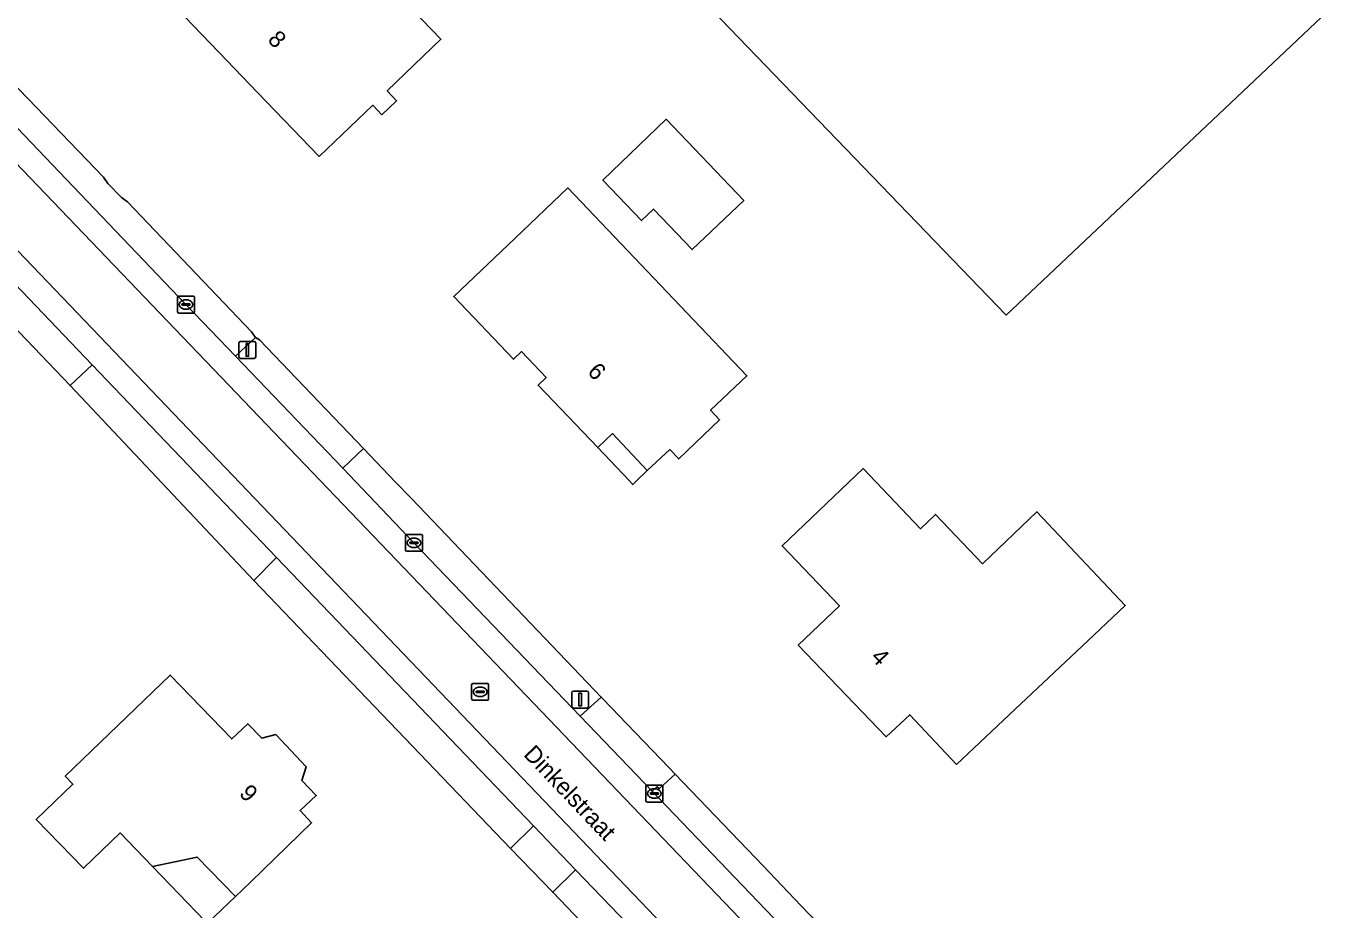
# Model space of a CAD drawing. Extents: x 156702 to 158052, y 387630 to 388992.
# Drawn here: x 157527.1 to 157604.6, y 388153.2 to 388205.4 of the extents above; entities that cross this region are included whole.
import ezdxf

# ---------------------------------------------------------------- set-up
doc = ezdxf.new("R2010")
doc.units = 0
for name, color, linetype in [('IMGEO_Erf', 7, 'Continuous'), ('IMGEO_Kolk', 7, 'Continuous'), ('IMGEO_Lichtmast', 7, 'Continuous'), ('IMGEO_Openbare_ruimte_label', 7, 'Continuous'), ('IMGEO_Pand', 7, 'Continuous'), ('IMGEO_Pand_nummerreeks', 7, 'Continuous'), ('IMGEO_Pand_overbouw', 7, 'Continuous'), ('IMGEO_Rijbaan_lokaal_open', 7, 'Continuous'), ('IMGEO_Rioolput', 7, 'Continuous'), ('IMGEO_Voetpad_open', 7, 'Continuous')]:
    doc.layers.add(name, color=color, linetype=linetype)

msp = doc.modelspace()

# ---------------------------------------------------------------- linework, layer by layer
at = {"layer": 'IMGEO_Erf'}
for points in [[(157584.886, 388188.316), (157564.394, 388209.598), (157567.99, 388213.072), (157562.196, 388219.112), (157558.734, 388222.72), (157562.775, 388226.601), (157551.074, 388238.835), (157562.705, 388250), (157570.484, 388257.467), (157577.622, 388250), (157591.461, 388235.522), (157612.045, 388213.988), (157596.348, 388199.15)], [(157545.965, 388213.543), (157545.335, 388214.2), (157543.747, 388212.677), (157544.379, 388212.022), (157551.546, 388204.59), (157548.388, 388201.538), (157548.939, 388200.958), (157548.07, 388200.135), (157547.532, 388200.697), (157544.359, 388197.674), (157540.74, 388201.439), (157538.454, 388203.818), (157534.94, 388207.473), (157540.5, 388212.859), (157537.541, 388215.969), (157551.018, 388228.911), (157554.477, 388225.3), (157556.264, 388223.433)], [(157566.379, 388192.175), (157564.095, 388194.571), (157563.378, 388193.888), (157561.103, 388196.275), (157564.843, 388199.867), (157569.417, 388195.069)], [(157565.575, 388179.831), (157565.045, 388180.385), (157563.721, 388179.149), (157561.668, 388181.325), (157560.8, 388180.496), (157557.278, 388184.182), (157557.755, 388184.638), (157556.31, 388186.168), (157555.825, 388185.706), (157552.312, 388189.403), (157555.931, 388192.854), (157559.037, 388195.816), (157569.604, 388184.732), (157567.454, 388182.7), (157567.987, 388182.144)], [(157591.917, 388171.185), (157589.715, 388169.11), (157585.761, 388165.385), (157581.966, 388161.809), (157579.203, 388164.742), (157577.82, 388163.439), (157572.633, 388168.85), (157575.055, 388171.164), (157571.677, 388174.7), (157576.449, 388179.259), (157579.834, 388175.716), (157580.716, 388176.559), (157583.493, 388173.652), (157586.703, 388176.719)], [(157527.679, 388158.56), (157529.838, 388160.644), (157529.388, 388161.112), (157531.985, 388163.611), (157535.587, 388167.077), (157539.209, 388163.312), (157540.154, 388164.212), (157540.984, 388163.354), (157541.807, 388163.566), (157543.605, 388161.659), (157543.353, 388160.859), (157544.195, 388159.985), (157543.24, 388159.084), (157543.921, 388158.367), (157540.331, 388154.888), (157539.431, 388154.015), (157537.169, 388156.349), (157534.533, 388155.796), (157532.623, 388157.774), (157530.457, 388155.683)]]:
    msp.add_lwpolyline(points, close=True, dxfattribs=at)
for points in [[(157587.035, 388124.121), (157579.276, 388132.213), (157572.963, 388138.799), (157564.783, 388147.336), (157558.148, 388154.267), (157555.656, 388156.858), (157540.509, 388172.666), (157529.678, 388184.162), (157518.473, 388195.859), (157513.847, 388200.675), (157504.663, 388210.298), (157501.613, 388213.475), (157500.203, 388214.779)], [(157525.186, 388203.161), (157531.652, 388196.446), (157531.904, 388196.084), (157532.708, 388195.257), (157533.058, 388194.995), (157540.381, 388187.324), (157540.603, 388187.003), (157540.852, 388186.863), (157546.974, 388180.453), (157548.872, 388178.469), (157549.792, 388177.507), (157561.008, 388165.78), (157561.677, 388165.081), (157562.03, 388164.713), (157565.006, 388161.615), (157565.368, 388161.238), (157570.562, 388155.83), (157572.789, 388153.497), (157573.82, 388152.417), (157574.214, 388152.004), (157593.208, 388132.152), (157609.438, 388115.184)]]:
    msp.add_lwpolyline(points, dxfattribs=at)
at = {"layer": 'IMGEO_Kolk'}
for p, q in [((157536.008, 388188.512), (157536.008, 388189.364)), ((157536.083, 388189.438), (157536.935, 388189.438)), ((157536.267, 388188.932), (157536.267, 388188.944)), ((157536.705, 388188.895), (157536.307, 388188.895)), ((157536.31, 388188.981), (157536.708, 388188.981)), ((157536.496, 388189.218), (157536.521, 388189.218)), ((157536.751, 388188.944), (157536.751, 388188.932)), ((157537.009, 388189.364), (157537.009, 388188.512)), ((157536.935, 388188.438), (157536.083, 388188.438)), ((157536.519, 388188.658), (157536.494, 388188.658)), ((157549.461, 388174.455), (157549.461, 388175.307)), ((157549.536, 388175.381), (157550.388, 388175.381)), ((157549.72, 388174.875), (157549.72, 388174.887)), ((157550.158, 388174.838), (157549.76, 388174.838)), ((157549.763, 388174.924), (157550.161, 388174.924)), ((157549.949, 388175.161), (157549.974, 388175.161)), ((157550.204, 388174.887), (157550.204, 388174.875)), ((157550.462, 388175.307), (157550.462, 388174.455)), ((157550.388, 388174.381), (157549.536, 388174.381)), ((157549.972, 388174.601), (157549.947, 388174.601)), ((157563.642, 388159.666), (157563.642, 388160.518)), ((157563.717, 388160.592), (157564.569, 388160.592)), ((157563.901, 388160.086), (157563.901, 388160.098)), ((157563.944, 388160.135), (157564.342, 388160.135)), ((157564.13, 388160.372), (157564.155, 388160.372)), ((157564.385, 388160.098), (157564.385, 388160.086)), ((157564.643, 388160.518), (157564.643, 388159.666)), ((157564.569, 388159.592), (157563.717, 388159.592)), ((157564.339, 388160.049), (157563.941, 388160.049)), ((157564.153, 388159.812), (157564.128, 388159.812))]:
    msp.add_line(p, q, dxfattribs=at)
for points in [[(157536.008, 388188.512), (157536.008, 388189.364)], [(157536.083, 388189.438), (157536.935, 388189.438)], [(157537.009, 388189.364), (157537.009, 388188.512)], [(157536.935, 388188.438), (157536.083, 388188.438)], [(157549.461, 388174.455), (157549.461, 388175.307)], [(157549.536, 388175.381), (157550.388, 388175.381)], [(157550.462, 388175.307), (157550.462, 388174.455)], [(157550.388, 388174.381), (157549.536, 388174.381)], [(157563.642, 388159.666), (157563.642, 388160.518)], [(157563.717, 388160.592), (157564.569, 388160.592)], [(157564.643, 388160.518), (157564.643, 388159.666)], [(157564.569, 388159.592), (157563.717, 388159.592)]]:
    msp.add_lwpolyline(points, dxfattribs=at)
for centre, radius, start, end in [((157536.085, 388189.362), 0.0765, 91.55205, 178.44795), ((157536.085, 388189.362), 0.0765, 91.55205, 178.44795), ((157536.307, 388188.941), 0.0403, 85.87752, 175.75265), ((157536.304, 388188.931), 0.0366, 178.93798, 274.71019), ((157536.708, 388188.938), 0.043, 264.86636, 352.45326), ((157536.712, 388188.943), 0.0386, 1.73085, 96.63898), ((157536.933, 388189.362), 0.0765, 1.55205, 88.44795), ((157536.933, 388189.362), 0.0765, 1.55205, 88.44795), ((157536.085, 388188.514), 0.0765, 181.55205, 268.44795), ((157536.085, 388188.514), 0.0765, 181.55205, 268.44795), ((157536.933, 388188.514), 0.0765, 271.55205, 358.44795), ((157536.933, 388188.514), 0.0765, 271.55205, 358.44795), ((157549.538, 388175.305), 0.0765, 91.55205, 178.44795), ((157549.538, 388175.305), 0.0765, 91.55205, 178.44795), ((157549.76, 388174.884), 0.0403, 85.87752, 175.75265), ((157549.757, 388174.874), 0.0366, 178.93798, 274.71019), ((157550.161, 388174.881), 0.043, 264.86636, 352.45326), ((157550.165, 388174.886), 0.0386, 1.73085, 96.63898), ((157550.386, 388175.305), 0.0765, 1.55205, 88.44795), ((157550.386, 388175.305), 0.0765, 1.55205, 88.44795), ((157549.538, 388174.457), 0.0765, 181.55205, 268.44795), ((157549.538, 388174.457), 0.0765, 181.55205, 268.44795), ((157550.386, 388174.457), 0.0765, 271.55205, 358.44795), ((157550.386, 388174.457), 0.0765, 271.55205, 358.44795), ((157563.719, 388160.516), 0.0765, 91.55205, 178.44795), ((157563.719, 388160.516), 0.0765, 91.55205, 178.44795), ((157563.941, 388160.095), 0.0403, 85.87752, 175.75265), ((157563.938, 388160.085), 0.0366, 178.93798, 274.71019), ((157564.342, 388160.092), 0.043, 264.86636, 352.45326), ((157564.346, 388160.097), 0.0386, 1.73085, 96.63898), ((157564.567, 388160.516), 0.0765, 1.55205, 88.44795), ((157564.567, 388160.516), 0.0765, 1.55205, 88.44795), ((157563.719, 388159.668), 0.0765, 181.55205, 268.44795), ((157563.719, 388159.668), 0.0765, 181.55205, 268.44795), ((157564.567, 388159.668), 0.0765, 271.55205, 358.44795), ((157564.567, 388159.668), 0.0765, 271.55205, 358.44795)]:
    msp.add_arc(centre, radius, start, end, dxfattribs=at)
for centre, major_axis, ratio, start_param, end_param in [((157536.495, 388188.938), (-0.387, 0.002), 0.722429, 4.712389, 7.853982), ((157536.52, 388188.938), (-0.39, 0.002), 0.717154, 1.570796, 4.712389), ((157549.948, 388174.881), (-0.387, 0.002), 0.722429, 4.712389, 7.853982), ((157549.973, 388174.881), (-0.39, 0.002), 0.717154, 1.570796, 4.712389), ((157564.129, 388160.092), (-0.387, 0.002), 0.722429, 4.712389, 7.853982), ((157564.154, 388160.092), (-0.39, 0.002), 0.717154, 1.570796, 4.712389)]:
    msp.add_ellipse(centre, major_axis=major_axis, ratio=ratio, start_param=start_param, end_param=end_param, dxfattribs=at)
at = {"layer": 'IMGEO_Lichtmast'}
for p, q in [((157539.635, 388185.863), (157539.635, 388186.663)), ((157539.635, 388186.663), (157539.635, 388185.863)), ((157539.735, 388186.763), (157540.525, 388186.763)), ((157540.525, 388186.763), (157539.735, 388186.763)), ((157540.625, 388186.663), (157540.625, 388185.863)), ((157540.625, 388185.863), (157540.625, 388186.663)), ((157540.525, 388185.763), (157539.735, 388185.763)), ((157539.735, 388185.763), (157540.525, 388185.763)), ((157559.269, 388165.233), (157559.269, 388166.033)), ((157559.269, 388166.033), (157559.269, 388165.233)), ((157559.369, 388166.133), (157560.159, 388166.133)), ((157560.159, 388166.133), (157559.369, 388166.133)), ((157560.259, 388166.033), (157560.259, 388165.233)), ((157560.259, 388165.233), (157560.259, 388166.033)), ((157560.159, 388165.133), (157559.369, 388165.133)), ((157559.369, 388165.133), (157560.159, 388165.133))]:
    msp.add_line(p, q, dxfattribs=at)
for points in [[(157540.055, 388186.638), (157540.205, 388186.638), (157540.205, 388185.888), (157540.055, 388185.888), (157540.055, 388186.638)], [(157559.689, 388166.008), (157559.839, 388166.008), (157559.839, 388165.258), (157559.689, 388165.258), (157559.689, 388166.008)]]:
    msp.add_lwpolyline(points, dxfattribs=at)
for centre, start, end in [((157539.735, 388186.663), 90, 180), ((157539.735, 388186.663), 90, 180), ((157540.525, 388186.663), 0, 90), ((157540.525, 388186.663), 360, 90), ((157539.735, 388185.863), 180, 270), ((157539.735, 388185.863), 180, 270), ((157540.525, 388185.863), 270, 0), ((157540.525, 388185.863), 270, 0), ((157559.369, 388166.033), 90, 180), ((157559.369, 388166.033), 90, 180), ((157560.159, 388166.033), 0, 90), ((157560.159, 388166.033), 360, 90), ((157559.369, 388165.233), 180, 270), ((157559.369, 388165.233), 180, 270), ((157560.159, 388165.233), 270, 0), ((157560.159, 388165.233), 270, 0)]:
    msp.add_arc(centre, 0.1, start, end, dxfattribs=at)
at = {"layer": 'IMGEO_Pand'}
for points in [[(157567.99, 388213.072), (157564.394, 388209.598), (157584.886, 388188.316), (157596.348, 388199.15), (157612.045, 388213.988), (157591.461, 388235.522)], [(157538.454, 388203.818), (157540.74, 388201.439), (157544.359, 388197.674), (157547.532, 388200.697), (157548.07, 388200.135), (157548.939, 388200.958), (157548.388, 388201.538), (157551.546, 388204.59), (157544.379, 388212.022), (157543.747, 388212.677), (157545.335, 388214.2), (157545.965, 388213.543), (157556.264, 388223.433), (157554.477, 388225.3), (157551.018, 388228.911), (157537.541, 388215.969), (157540.5, 388212.859), (157534.94, 388207.473)], [(157563.378, 388193.888), (157564.095, 388194.571), (157566.379, 388192.175), (157569.417, 388195.069), (157564.843, 388199.867), (157561.103, 388196.275)], [(157560.8, 388180.496), (157561.668, 388181.325), (157563.721, 388179.149), (157565.045, 388180.385), (157565.575, 388179.831), (157567.987, 388182.144), (157567.454, 388182.7), (157569.604, 388184.732), (157559.037, 388195.816), (157555.931, 388192.854), (157552.312, 388189.403), (157555.825, 388185.706), (157556.31, 388186.168), (157557.755, 388184.638), (157557.278, 388184.182)], [(157589.715, 388169.11), (157591.917, 388171.185), (157586.703, 388176.719), (157583.493, 388173.652), (157580.716, 388176.559), (157579.834, 388175.716), (157576.449, 388179.259), (157571.677, 388174.7), (157575.055, 388171.164), (157572.633, 388168.85), (157577.82, 388163.439), (157579.203, 388164.742), (157581.966, 388161.809), (157585.761, 388165.385)], [(157539.431, 388154.015), (157540.331, 388154.888), (157543.921, 388158.367), (157543.24, 388159.084), (157544.195, 388159.985), (157543.353, 388160.859), (157543.605, 388161.659), (157541.807, 388163.566), (157540.984, 388163.354), (157540.154, 388164.212), (157539.209, 388163.312), (157535.587, 388167.077), (157531.985, 388163.611), (157529.388, 388161.112), (157529.838, 388160.644), (157527.679, 388158.56), (157530.457, 388155.683), (157532.623, 388157.774), (157534.533, 388155.796), (157537.169, 388156.349)]]:
    msp.add_lwpolyline(points, close=True, dxfattribs=at)
at = {"layer": 'IMGEO_Pand_overbouw'}
for points in [[(157560.8, 388180.496), (157562.651, 388178.554), (157562.864, 388178.322), (157563.093, 388178.539), (157563.721, 388179.149), (157561.668, 388181.325)], [(157534.533, 388155.796), (157537.649, 388152.569), (157537.775, 388152.439), (157539.431, 388154.015), (157537.169, 388156.349)]]:
    msp.add_lwpolyline(points, close=True, dxfattribs=at)
at = {"layer": 'IMGEO_Rijbaan_lokaal_open'}
for points in [[(157609.911, 388112.196), (157591.786, 388131.202), (157577.621, 388146.005), (157573.012, 388150.836), (157569.341, 388154.667), (157564.008, 388160.23), (157559.757, 388164.664), (157549.961, 388174.881), (157545.763, 388179.279), (157539.44, 388185.889), (157536.509, 388188.937), (157524.471, 388201.521), (157523.994, 388202.001), (157516.86, 388209.457), (157516.607, 388209.721), (157507.617, 388218.991), (157506.291, 388220.397), (157505.252, 388219.445), (157569.611, 388152.266), (157609.631, 388110.47)], [(157624.063, 388095.085), (157622.801, 388096.503), (157622.266, 388097.074), (157611.799, 388108.253), (157611.22, 388108.439), (157611.207, 388108.452), (157610.633, 388109.036), (157609.788, 388109.895), (157609.631, 388110.47), (157569.611, 388152.266), (157505.252, 388219.445), (157502.666, 388217.076), (157520.881, 388198.047), (157571.193, 388145.504), (157602.434, 388112.73)], [(157520.881, 388198.047), (157502.666, 388217.076), (157501.5, 388216.007), (157502.813, 388214.652), (157503.415, 388215.215), (157506.471, 388212.039), (157505.936, 388211.53), (157515.137, 388201.917), (157519.764, 388197.104), (157530.97, 388185.39), (157541.858, 388174.01), (157557.021, 388158.183), (157559.496, 388155.588), (157566.169, 388148.651), (157574.344, 388140.111), (157580.64, 388133.535), (157588.386, 388125.454), (157602.101, 388110.987), (157604.416, 388109.059)], [(157602.434, 388112.73), (157571.193, 388145.504), (157520.881, 388198.047)]]:
    msp.add_lwpolyline(points, dxfattribs=at)
at = {"layer": 'IMGEO_Rioolput'}
for p, q in [((157553.364, 388165.666), (157553.364, 388166.518)), ((157553.439, 388166.592), (157554.291, 388166.592)), ((157553.852, 388166.372), (157553.877, 388166.372)), ((157554.365, 388166.518), (157554.365, 388165.666)), ((157554.291, 388165.592), (157553.439, 388165.592)), ((157553.623, 388166.086), (157553.623, 388166.098)), ((157554.061, 388166.049), (157553.663, 388166.049)), ((157553.666, 388166.135), (157554.064, 388166.135)), ((157553.875, 388165.812), (157553.85, 388165.812)), ((157554.107, 388166.098), (157554.107, 388166.086))]:
    msp.add_line(p, q, dxfattribs=at)
for points in [[(157553.364, 388165.666), (157553.364, 388166.518)], [(157553.439, 388166.592), (157554.291, 388166.592)], [(157554.365, 388166.518), (157554.365, 388165.666)], [(157554.291, 388165.592), (157553.439, 388165.592)]]:
    msp.add_lwpolyline(points, dxfattribs=at)
for centre, radius, start, end in [((157553.441, 388166.516), 0.0765, 91.55205, 178.44795), ((157553.441, 388166.516), 0.0765, 91.55205, 178.44795), ((157554.289, 388166.516), 0.0765, 1.55205, 88.44795), ((157554.289, 388166.516), 0.0765, 1.55205, 88.44795), ((157553.441, 388165.668), 0.0765, 181.55205, 268.44795), ((157553.441, 388165.668), 0.0765, 181.55205, 268.44795), ((157553.663, 388166.095), 0.0403, 85.87752, 175.75265), ((157553.66, 388166.085), 0.0366, 178.93798, 274.71019), ((157554.064, 388166.092), 0.043, 264.86636, 352.45326), ((157554.068, 388166.097), 0.0386, 1.73085, 96.63898), ((157554.289, 388165.668), 0.0765, 271.55205, 358.44795), ((157554.289, 388165.668), 0.0765, 271.55205, 358.44795)]:
    msp.add_arc(centre, radius, start, end, dxfattribs=at)
for centre, major_axis, ratio, start_param, end_param in [((157553.851, 388166.092), (-0.387, 0.002), 0.722429, 4.712389, 7.853982), ((157553.876, 388166.092), (-0.39, 0.002), 0.717154, 1.570796, 4.712389)]:
    msp.add_ellipse(centre, major_axis=major_axis, ratio=ratio, start_param=start_param, end_param=end_param, dxfattribs=at)
at = {"layer": 'IMGEO_Voetpad_open'}
for points in [[(157524.471, 388201.521), (157536.509, 388188.937), (157539.44, 388185.889), (157540.603, 388187.003), (157540.381, 388187.324), (157533.058, 388194.995), (157532.708, 388195.257), (157531.904, 388196.084), (157531.652, 388196.446), (157525.186, 388203.161), (157523.994, 388202.001)], [(157530.97, 388185.39), (157519.764, 388197.104), (157518.473, 388195.859), (157529.678, 388184.162)], [(157545.763, 388179.279), (157546.974, 388180.453), (157540.852, 388186.863), (157540.603, 388187.003), (157539.44, 388185.889)], [(157530.97, 388185.39), (157529.678, 388184.162), (157540.509, 388172.666), (157541.858, 388174.01)], [(157548.872, 388178.469), (157546.974, 388180.453), (157545.763, 388179.279), (157549.961, 388174.881), (157559.757, 388164.664), (157561.008, 388165.78), (157549.792, 388177.507)], [(157540.509, 388172.666), (157555.656, 388156.858), (157557.021, 388158.183), (157541.858, 388174.01)], [(157561.008, 388165.78), (157559.757, 388164.664), (157564.008, 388160.23), (157564.295, 388160.496), (157564.437, 388160.383), (157565.368, 388161.238), (157565.006, 388161.615), (157562.03, 388164.713), (157561.677, 388165.081)], [(157574.214, 388152.004), (157573.82, 388152.417), (157572.789, 388153.497), (157570.562, 388155.83), (157565.368, 388161.238), (157564.437, 388160.383), (157564.295, 388160.496), (157564.008, 388160.23), (157569.341, 388154.667), (157573.012, 388150.836), (157577.621, 388146.005), (157591.786, 388131.202), (157609.911, 388112.196), (157611.15, 388113.418), (157609.438, 388115.184), (157593.208, 388132.152)], [(157559.496, 388155.588), (157557.021, 388158.183), (157555.656, 388156.858), (157558.148, 388154.267)], [(157559.496, 388155.588), (157558.148, 388154.267), (157564.783, 388147.336), (157566.169, 388148.651)]]:
    msp.add_lwpolyline(points, close=True, dxfattribs=at)

# ---------------------------------------------------------------- texts
at = {"layer": 'IMGEO_Openbare_ruimte_label'}
msp.add_text('Dinkelstraat', height=1, rotation=313.54158, dxfattribs=at).set_placement((157556.372, 388162.36))
at = {"layer": 'IMGEO_Pand_nummerreeks'}
for s, rotation, p in [('8', 313.86723, (157541.278, 388204.516)), ('6', 313.6966, (157560.142, 388184.927)), ('4', 313.78917, (157576.855, 388168.087)), ('9', 313.51611, (157539.6, 388160.048))]:
    msp.add_text(s, height=1, rotation=rotation, dxfattribs=at).set_placement(p)

doc.saveas('drawing.dxf')
